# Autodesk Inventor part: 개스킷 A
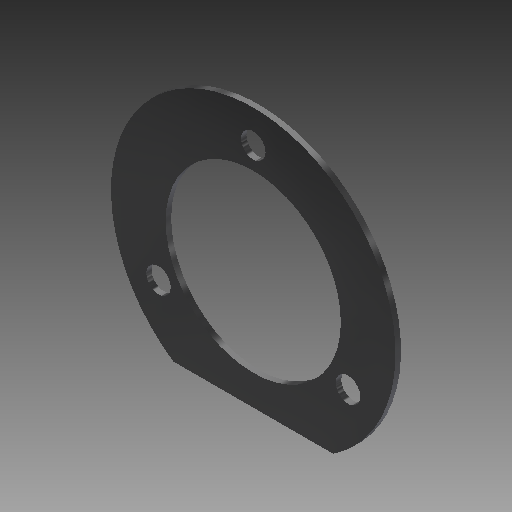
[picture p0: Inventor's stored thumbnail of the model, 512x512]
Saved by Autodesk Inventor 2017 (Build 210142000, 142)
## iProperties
Created: 2020-04
Part Number: 개스킷 A
Material: 고무
Document SubType Name: Modeling
Designer: mduedu
Density: 0.93 g/cm^3
Appearance: 고무 - 검은색 - 버전 1.1
Mass: 1.09963 g
Surface Area: 26.6928 cm^2
Volume: 1.18239 cm^3
Author: mduedu
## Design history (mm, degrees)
sketch "스케치1"
  geometry: C1 r 26 at (0, 0); 1 further point
  constraints: 1 centre point, 1 coincident
  dimensions: "d0" = 52 diameter of C1
extrude "돌출1" new body sketch "스케치1" distance "d1" = 1; taper "d2" = 0 deg
sketch "스케치2"
  geometry: L1 (-14.62, -21.5)-(14.62, -21.5); A1 r 26 centre (0, 0) between (-14.62, -21.5) and (14.62, -21.5) reference; 1 further point
  constraints: 2 end point, 2 point on circle, 1 horizontal
  dimensions: "d3" = 21.5 distance from line of L1 point (0, 0)
extrude "돌출2" cut sketch "스케치2" stored distance "d4" = 1; taper "d5" = 0 deg
sketch "스케치3" dims "d6" = 40
  geometry: 3 further points
  constraints: 2 vertical alignment, 1 coincident, 2 other
hole "구멍1" sketch "스케치3" at (0, 20) diameter "d7" = 4.5; stored, may be unused: countersink angle "d11" = 90 deg, drill point angle "d13" = 118 deg; dims "d8" = 6, "d9" = 4, "d10" = 2, "d12" = 8
sketch "스케치4"
  geometry: C1 r 16 at (0, 0); 1 further point
  constraints: 1 centre point, 1 coincident
  dimensions: "d17" = 32 diameter of C1
extrude "돌출3" cut sketch "스케치4" stored distance "d18" = 1; taper "d19" = 0 deg
node "솔리드1"
pattern_circular "원형 패턴1" dims angle "d15" = 360 deg
node "투영된 루프1"
